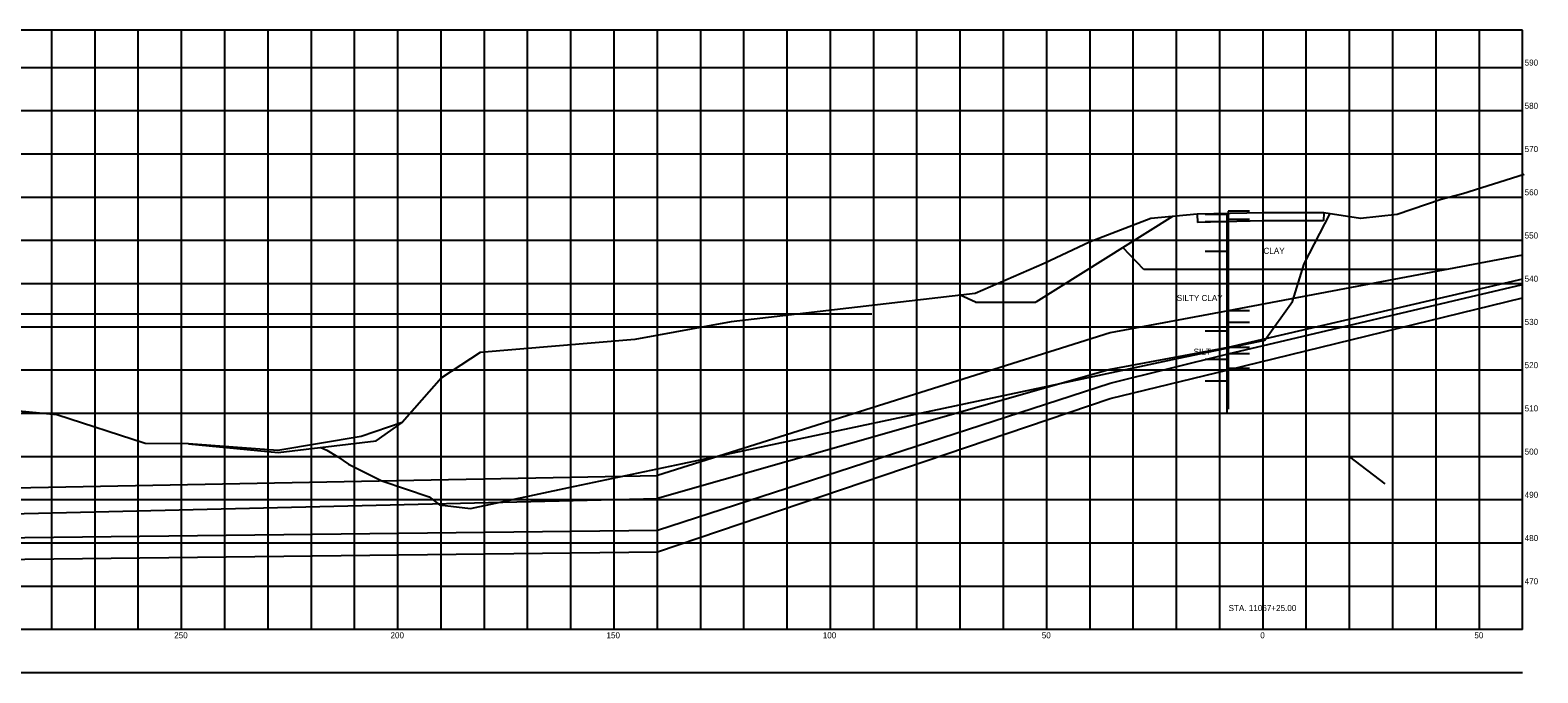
# Model space of a CAD drawing. Extents: x -64 to 1064, y -32 to 640.
# Drawn here: x 715 to 1063.5, y 1.8 to 150.5 of the extents above; entities that cross this region are included whole.
import ezdxf

# ---------------------------------------------------------------- set-up
doc = ezdxf.new("R2010")
doc.units = 0
for name, color, linetype in [('GT_Project_Soil_Boring', 7, 'Continuous'), ('GT_Project_Soil_Layers', 7, 'Continuous'), ('GT_X_Shear_Surface', 7, 'Continuous'), ('SC_Scratch1', 7, 'Continuous'), ('SH_Major_Grid_Line', 7, 'Continuous'), ('SH_Text', 7, 'Continuous')]:
    doc.layers.add(name, color=color, linetype=linetype)

msp = doc.modelspace()

# ---------------------------------------------------------------- linework, layer by layer
at = {"layer": 'GT_Project_Soil_Boring'}
for p, q in [((991.9, 108.55), (991.9, 62.76)), ((996.9, 108.55), (991.9, 108.55)), ((986.6, 107.85), (991.6, 107.85)), ((986.6, 106.15), (991.6, 106.15)), ((991.6, 107.85), (991.6, 62.08)), ((996.9, 106.65), (991.9, 106.65)), ((986.6, 99.35), (991.6, 99.35)), ((996.9, 95.05), (991.9, 95.05)), ((996.9, 85.55), (991.9, 85.55)), ((986.6, 80.85), (991.6, 80.85)), ((996.9, 82.85), (991.9, 82.85)), ((996.9, 77.05), (991.9, 77.05)), ((986.6, 74.35), (991.6, 74.35)), ((996.9, 75.55), (991.9, 75.55))]:
    msp.add_line(p, q, dxfattribs=at)
at = {"layer": 'GT_Project_Soil_Layers'}
for p, q in [((1014.08, 108.22), (1013.98, 106.32)), ((979.05, 107.35), (947.47, 87.54)), ((984.75, 107.86), (984.85, 105.96)), ((972.41, 95.05), (967.61, 100.17)), ((1042.39, 95.05), (972.41, 95.05)), ((933.5, 87.54), (930, 89.14)), ((933.5, 87.54), (947.47, 87.54)), ((996.9, 72.15), (991.9, 72.15)), ((986.6, 69.35), (991.6, 69.35)), ((660, 43.59), (860, 47.44)), ((660, 37.36), (860, 42.12)), ((660, 32.45), (860, 34.75)), ((660, 27.45), (860, 29.75))]:
    msp.add_line(p, q, dxfattribs=at)
for points in [[(1014.08, 108.22), (1000, 108.21), (984.75, 107.86)], [(1013.98, 106.32), (1000, 106.31), (984.85, 105.96)], [(1060, 98.37), (991.9, 85.55), (964.69, 80.43), (860, 47.44)], [(1060, 92.82), (991.9, 77.05), (964.69, 71.93), (860, 42.12)], [(860, 34.75), (964.69, 68.75), (991.9, 75.55), (1060, 91.64)], [(860, 29.75), (964.69, 65.25), (991.9, 71.9), (1060, 88.55)]]:
    msp.add_lwpolyline(points, dxfattribs=at)
at = {"layer": 'GT_X_Shear_Surface'}
msp.add_lwpolyline([(782.23, 53.93), (783.56, 53.28), (786.1, 51.7), (788.6, 50.04), (796.3, 46.16), (807.26, 42.52), (809.6, 40.64), (816.8, 39.79), (839.5, 44.61), (865.9, 50.21), (960.7, 70.33), (979.1, 74.23), (990.51, 76.65), (1000.43, 78.75), (1006.78, 87.65), (1009.49, 96.38), (1015.48, 108.02)], dxfattribs=at)
at = {"layer": 'SC_Scratch1'}
for p, q in [((909.57, 84.75), (628.77, 84.75)), ((1020, 51.75), (1028.17, 45.49))]:
    msp.add_line(p, q, dxfattribs=at)
for points in [[(1060.34, 117.09), (1046.19, 112.61), (1041.14, 111.26), (1031.04, 107.84), (1022.54, 106.84), (1014.08, 108.22), (1000.1, 108.21), (984.75, 107.86), (974.05, 106.9), (960.03, 101.49), (949.37, 96.46), (933.45, 89.52), (877.04, 82.98), (854.76, 78.88), (819.06, 75.85), (810.1, 70.04), (801.03, 59.71), (791.54, 56.43), (772.26, 53.2), (751.61, 54.76), (741.55, 54.82), (721.15, 61.42), (710.8, 62.47)], [(751.61, 54.76), (772.3, 52.75), (795, 55.45), (801.03, 59.71)]]:
    msp.add_lwpolyline(points, dxfattribs=at)
at = {"layer": 'SH_Major_Grid_Line'}
for p, q in [((1060, 150.46), (660, 150.46)), ((720, 11.75), (720, 150.46)), ((730, 11.75), (730, 150.46)), ((740, 11.75), (740, 150.46)), ((750, 11.75), (750, 150.46)), ((760, 11.75), (760, 150.46)), ((770, 11.75), (770, 150.46)), ((780, 11.75), (780, 150.46)), ((790, 11.75), (790, 150.46)), ((800, 11.75), (800, 150.46)), ((810, 11.75), (810, 150.46)), ((820, 11.75), (820, 150.46)), ((830, 11.75), (830, 150.46)), ((840, 11.75), (840, 150.46)), ((850, 11.75), (850, 150.46)), ((860, 11.75), (860, 150.46)), ((870, 11.75), (870, 150.46)), ((880, 11.75), (880, 150.46)), ((890, 11.75), (890, 150.46)), ((900, 11.75), (900, 150.46)), ((910, 11.75), (910, 150.46)), ((920, 11.75), (920, 150.46)), ((930, 11.75), (930, 150.46)), ((940, 11.75), (940, 150.46)), ((950, 11.75), (950, 150.46)), ((960, 11.75), (960, 150.46)), ((970, 11.75), (970, 150.46)), ((980, 11.75), (980, 150.46)), ((990, 11.75), (990, 150.46)), ((1000, 11.75), (1000, 150.46)), ((1010, 11.75), (1010, 150.46)), ((1020, 11.75), (1020, 150.46)), ((1030, 11.75), (1030, 150.46)), ((1040, 11.75), (1040, 150.46)), ((1050, 11.75), (1050, 150.46)), ((1060, 11.75), (1060, 150.46)), ((1060, 141.75), (660, 141.75)), ((1060, 131.75), (660, 131.75)), ((1060, 121.75), (660, 121.75)), ((1060, 111.75), (660, 111.75)), ((1060, 101.75), (660, 101.75)), ((1060, 91.75), (660, 91.75)), ((1060, 81.75), (660, 81.75)), ((1060, 71.75), (660, 71.75)), ((1060, 61.75), (660, 61.75)), ((1060, 51.75), (660, 51.75)), ((1060, 41.75), (660, 41.75)), ((1060, 31.75), (660, 31.75)), ((1060, 21.75), (660, 21.75)), ((1060, 11.75), (660, 11.75)), ((1060, 1.75), (660, 1.75))]:
    msp.add_line(p, q, dxfattribs=at)

# ---------------------------------------------------------------- texts
at = {"layer": 'GT_Project_Soil_Boring'}
for s, p in [('CLAY', (1000.1, 98.7)), ('SILTY CLAY', (980.06, 87.8)), ('SILT', (983.96, 75.37))]:
    msp.add_text(s, height=1.4, dxfattribs=at).set_placement(p)
at = {"layer": 'SH_Text'}
for s, p in [('590', (1060.47, 142.25)), ('580', (1060.47, 132.25)), ('570', (1060.47, 122.25)), ('560', (1060.47, 112.25)), ('550', (1060.47, 102.25)), ('540', (1060.47, 92.25)), ('530', (1060.47, 82.25)), ('520', (1060.47, 72.25)), ('510', (1060.47, 62.25)), ('500', (1060.47, 52.25)), ('490', (1060.48, 42.25)), ('480', (1060.48, 32.25)), ('470', (1060.48, 22.25)), ('STA. 11067+25.00', (992.03, 16.05)), ('250', (748.29, 9.75)), ('200', (798.29, 9.75)), ('150', (848.22, 9.75)), ('100', (898.22, 9.75)), ('50', (948.85, 9.75)), ('0', (999.36, 9.75)), ('50', (1048.85, 9.75))]:
    msp.add_text(s, height=1.4, dxfattribs=at).set_placement(p)

doc.saveas('drawing.dxf')
